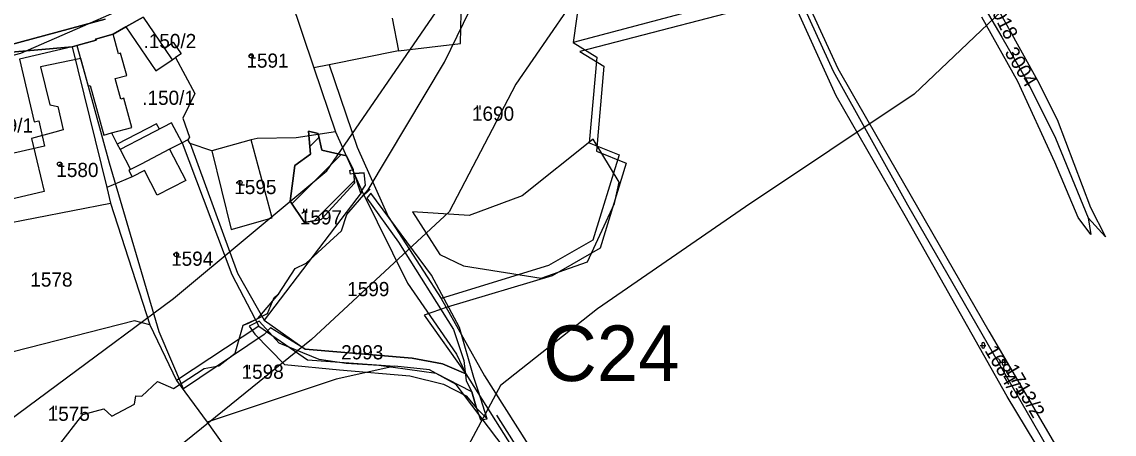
# Model space of a CAD drawing. Extents: x -564810 to -550519, y -1045831 to -1034011.
# Drawn here: x -554012.6 to -553619.6, y -1037838.1 to -1037689.8 of the extents above; entities that cross this region are included whole.
import ezdxf

# ---------------------------------------------------------------- set-up
doc = ezdxf.new("R2010")
doc.units = 0
for name, color, linetype in [('Interakční prvky', 7, 'Continuous'), ('KN stav', 7, 'Continuous'), ('Obvod KPU', 7, 'Continuous'), ('označ pol cest', 7, 'Continuous'), ('Parcelní čísla', 7, 'Continuous'), ('Polní cesty stavající', 7, 'Continuous'), ('STG', 7, 'Continuous'), ('Vodní plocha', 7, 'Continuous'), ('vodní toky', 7, 'Continuous'), ('Vrstva 22', 7, 'Continuous'), ('Vrstva 33', 7, 'Continuous'), ('Vrstva 4', 7, 'Continuous'), ('zamokř ploch', 7, 'Continuous')]:
    doc.layers.add(name, color=color, linetype=linetype)

msp = doc.modelspace()

# ---------------------------------------------------------------- linework, layer by layer
at = {"layer": 'Interakční prvky'}
msp.add_lwpolyline([(-553841.79, -1037831.23), (-553697.83, -1038058.69), (-553643.78, -1038106.7)], dxfattribs=at)
at = {"layer": 'KN stav'}
for p, q in [((-553854.73, -1037697.64), (-553853.8, -1037658.19)), ((-553743.64, -1037657.08), (-553720.71, -1037707.5)), ((-553741.77, -1037657.08), (-553719.06, -1037706.56)), ((-553674.89, -1037669.86), (-553660.06, -1037695.35)), ((-553810.8, -1037673.21), (-553814.25, -1037697.2)), ((-553668.6, -1037672.13), (-553647.19, -1037710.95)), ((-553917.01, -1037678.13), (-553907.55, -1037706.36)), ((-553737.54, -1037676.84), (-553814.25, -1037697.2)), ((-553719.66, -1037716.36), (-553737.54, -1037676.84)), ((-554016.74, -1037698.02), (-553982.63, -1037688.82)), ((-553982.63, -1037688.82), (-554016.74, -1037698.02)), ((-553968.97, -1037688.08), (-553975.14, -1037691.62)), ((-553975.14, -1037691.62), (-553968.97, -1037688.08)), ((-553968.97, -1037688.08), (-553961.29, -1037699.33)), ((-553879.38, -1037688.47), (-553877.01, -1037700.18)), ((-553654.3, -1037711.22), (-553667.19, -1037688.1)), ((-553979.72, -1037694.24), (-553986, -1037695.97)), ((-553986, -1037695.97), (-553979.72, -1037694.24)), ((-553975.14, -1037691.62), (-553979.72, -1037694.24)), ((-553979.72, -1037694.24), (-553975.14, -1037691.62)), ((-553975.14, -1037691.62), (-553964.35, -1037707.42)), ((-553660.06, -1037695.35), (-553650.86, -1037711.16)), ((-553994.44, -1037698.83), (-554017.69, -1037700.77)), ((-554017.69, -1037700.77), (-553994.44, -1037698.83)), ((-553994.44, -1037698.83), (-554013.39, -1037703.24)), ((-553992.75, -1037698.33), (-553994.44, -1037698.83)), ((-553994.44, -1037698.83), (-553992.75, -1037698.33)), ((-553994.44, -1037698.83), (-553981.94, -1037749.42)), ((-553985.87, -1037696.44), (-553992.75, -1037698.33)), ((-553992.75, -1037698.33), (-553985.87, -1037696.44)), ((-553986, -1037695.97), (-553985.87, -1037696.44)), ((-553985.87, -1037696.44), (-553986, -1037695.97)), ((-553961.29, -1037699.33), (-553958.09, -1037697.15)), ((-553958.09, -1037697.15), (-553955.29, -1037701.24)), ((-553877.01, -1037700.18), (-553854.73, -1037697.64)), ((-553814.25, -1037697.2), (-553805.69, -1037702.54)), ((-554013.39, -1037703.24), (-554008.14, -1037725.77)), ((-553958.5, -1037703.43), (-553957.3, -1037702.61)), ((-553955.29, -1037701.24), (-553957.3, -1037702.61)), ((-553957.3, -1037702.61), (-553950.35, -1037715.52)), ((-553877.01, -1037700.18), (-553902.01, -1037705.24)), ((-553805.69, -1037702.54), (-553808.47, -1037733.31)), ((-553964.35, -1037707.42), (-553958.5, -1037703.43)), ((-553902.01, -1037705.24), (-553907.55, -1037706.36)), ((-553907.55, -1037706.36), (-553899.71, -1037729.33)), ((-553902.01, -1037705.24), (-553891.9, -1037734.88)), ((-553719.06, -1037706.56), (-553708.21, -1037725.45)), ((-553720.71, -1037707.5), (-553693.99, -1037755.63)), ((-553647.19, -1037710.95), (-553640.1, -1037724.97)), ((-553640.99, -1037740.25), (-553654.3, -1037711.22)), ((-553650.86, -1037711.16), (-553640.66, -1037731.58)), ((-553950.35, -1037715.52), (-553954.66, -1037724.43)), ((-553694.81, -1037759.51), (-553719.66, -1037716.36)), ((-554008.14, -1037725.77), (-554006.43, -1037725.38)), ((-554006.43, -1037725.38), (-554004.37, -1037734.49)), ((-553954.66, -1037724.43), (-553952.25, -1037731.25)), ((-553708.21, -1037725.45), (-553664.67, -1037801.06)), ((-553640.1, -1037724.97), (-553628.11, -1037756.57)), ((-553899.71, -1037729.33), (-553913.84, -1037731.52)), ((-553899.71, -1037729.33), (-553890.08, -1037750.79)), ((-554004.37, -1037734.49), (-554015.4, -1037736.99)), ((-553954.93, -1037733.29), (-553959.4, -1037735.61)), ((-553952.8, -1037732.18), (-553954.93, -1037733.29)), ((-553954.93, -1037733.29), (-553937.07, -1037780.67)), ((-553952.25, -1037731.25), (-553952.8, -1037732.18)), ((-553952.03, -1037733.6), (-553952.8, -1037732.18)), ((-553944.16, -1037736.23), (-553952.03, -1037733.6)), ((-553952.03, -1037733.6), (-553935.01, -1037780.21)), ((-553930.11, -1037732.23), (-553944.16, -1037736.23)), ((-553927.85, -1037731.72), (-553930.11, -1037732.23)), ((-553922.54, -1037760.31), (-553930.11, -1037732.23)), ((-553913.84, -1037731.52), (-553927.85, -1037731.72)), ((-553808.47, -1037733.31), (-553797.69, -1037737.62)), ((-553640.66, -1037731.58), (-553629, -1037760.31)), ((-553959.4, -1037735.61), (-553953.57, -1037746.81)), ((-553944.16, -1037736.23), (-553937.26, -1037764.51)), ((-553891.9, -1037734.88), (-553880.74, -1037759.79)), ((-553797.69, -1037737.62), (-553807.14, -1037768.34)), ((-553632.56, -1037760.13), (-553640.99, -1037740.25)), ((-553972.82, -1037745.53), (-553981.94, -1037749.42)), ((-553968.44, -1037743.25), (-553972.82, -1037745.53)), ((-553963.82, -1037752.14), (-553968.44, -1037743.25)), ((-553981.94, -1037749.42), (-553980.7, -1037754.99)), ((-553953.57, -1037746.81), (-553963.82, -1037752.14)), ((-553890.08, -1037750.79), (-553925.39, -1037797.06)), ((-553890.08, -1037750.79), (-553873.82, -1037783.79)), ((-554041.33, -1037766.82), (-553980.7, -1037754.99)), ((-553980.7, -1037754.99), (-553966.52, -1037798.77)), ((-553693.99, -1037755.63), (-553650.89, -1037830.33)), ((-553628.11, -1037756.57), (-553622.69, -1037767.07)), ((-553937.26, -1037764.51), (-553922.54, -1037760.31)), ((-553880.74, -1037759.79), (-553861.7, -1037789.25)), ((-553658.07, -1037824.52), (-553694.81, -1037759.51)), ((-553627.94, -1037766.27), (-553632.56, -1037760.13)), ((-553629, -1037760.31), (-553627.94, -1037766.27)), ((-553622.69, -1037767.07), (-553629, -1037760.31)), ((-553807.14, -1037768.34), (-553823.05, -1037777.47)), ((-553823.05, -1037777.47), (-553861.7, -1037789.25)), ((-553937.07, -1037780.67), (-553927.36, -1037799.27)), ((-553935.01, -1037780.21), (-553925.39, -1037797.06)), ((-553873.82, -1037783.79), (-553856.17, -1037809.33)), ((-553861.7, -1037789.25), (-553846.17, -1037817.17)), ((-553972.08, -1037797.39), (-554044.67, -1037815.82)), ((-553966.52, -1037798.77), (-553972.08, -1037797.39)), ((-553925.39, -1037797.06), (-553910.62, -1037807.56)), ((-553966.52, -1037798.77), (-553956.87, -1037818.76)), ((-553927.36, -1037799.27), (-553956.87, -1037818.76)), ((-553927.36, -1037799.27), (-553909.76, -1037811.31)), ((-553664.67, -1037801.06), (-553629.03, -1037861.88)), ((-553910.62, -1037807.56), (-553872.1, -1037810.73)), ((-553856.17, -1037809.33), (-553852.8, -1037816.35)), ((-553909.76, -1037811.31), (-553878.32, -1037813.69)), ((-553872.1, -1037810.73), (-553861.26, -1037812.79)), ((-553861.26, -1037812.79), (-553852.8, -1037816.35)), ((-553878.32, -1037813.69), (-553899.52, -1037818.33)), ((-553865.96, -1037815), (-553878.32, -1037813.69)), ((-553856.36, -1037820.25), (-553865.96, -1037815)), ((-553852.8, -1037816.35), (-553821.18, -1037866.37)), ((-553846.17, -1037817.17), (-553818.67, -1037860.27)), ((-553956.87, -1037818.76), (-553945.89, -1037833.82)), ((-553899.52, -1037818.33), (-553945.89, -1037833.82)), ((-553821.18, -1037866.37), (-553856.36, -1037820.25)), ((-553638.92, -1037856.33), (-553658.07, -1037824.52)), ((-553650.89, -1037830.33), (-553618.97, -1037885.65)), ((-553945.89, -1037833.82), (-553940.01, -1037842.06))]:
    msp.add_line(p, q, dxfattribs=at)
at = {"layer": 'Obvod KPU'}
for p, q in [((-553736.67, -1037680.93), (-553811.81, -1037700.43)), ((-553991.33, -1037702.98), (-554005.84, -1037705.93)), ((-553981.07, -1037740.66), (-553991.33, -1037702.98)), ((-553811.81, -1037700.43), (-553803.16, -1037705.71)), ((-554005.84, -1037705.93), (-554002.49, -1037719.62)), ((-553803.16, -1037705.71), (-553805.84, -1037736.34)), ((-554002.49, -1037719.62), (-553999.57, -1037720.24)), ((-553999.57, -1037720.24), (-553997.7, -1037728.63)), ((-554000.69, -1037729.44), (-554009.13, -1037731.73)), ((-553997.7, -1037728.63), (-554000.69, -1037729.44)), ((-554009.13, -1037731.73), (-554007.22, -1037739.73)), ((-553805.84, -1037736.34), (-553795.21, -1037740.63)), ((-554007.22, -1037739.73), (-554004.57, -1037750.84)), ((-553963.1, -1037801.3), (-553981.07, -1037740.66)), ((-553795.21, -1037740.63), (-553804.53, -1037771.2)), ((-554004.57, -1037750.84), (-554026.81, -1037756.1)), ((-553804.53, -1037771.2), (-553821.75, -1037781.17)), ((-553821.75, -1037781.17), (-553859.61, -1037792.46)), ((-553859.61, -1037792.46), (-553867.77, -1037795.33)), ((-553867.77, -1037795.33), (-553852.8, -1037816.35)), ((-553954.36, -1037821.74), (-553963.1, -1037801.3)), ((-553923.06, -1037799.85), (-553925.39, -1037802.29)), ((-553910.62, -1037807.56), (-553923.06, -1037799.85)), ((-553925.39, -1037802.29), (-553954.36, -1037821.74)), ((-553872.1, -1037810.73), (-553910.62, -1037807.56)), ((-553861.26, -1037812.79), (-553872.1, -1037810.73)), ((-553852.8, -1037816.35), (-553861.26, -1037812.79))]:
    msp.add_line(p, q, dxfattribs=at)
at = {"layer": 'Polní cesty stavající'}
for p, q in [((-553892.98, -1037744.29), (-553889.4, -1037744.13)), ((-553889.4, -1037744.13), (-553892.98, -1037744.29)), ((-553892.98, -1037744.29), (-553890.76, -1037751.31)), ((-553888.93, -1037748.59), (-553889.4, -1037744.13)), ((-553890.76, -1037751.31), (-553888.93, -1037748.59)), ((-553886.98, -1037751.46), (-553888.48, -1037753.24)), ((-553888.48, -1037753.24), (-553877, -1037769.08)), ((-553865.14, -1037780.87), (-553886.98, -1037751.46)), ((-553877, -1037769.08), (-553857.27, -1037800.49)), ((-553855.06, -1037799.74), (-553865.14, -1037780.87)), ((-553857.27, -1037800.49), (-553853.5, -1037811.61)), ((-553849.96, -1037817.68), (-553855.06, -1037799.74)), ((-553853.5, -1037811.61), (-553852.76, -1037818.96)), ((-553852.76, -1037818.96), (-553850.68, -1037822.86)), ((-553848.24, -1037822.74), (-553849.96, -1037817.68)), ((-553845.14, -1037832.64), (-553848.24, -1037822.74))]:
    msp.add_line(p, q, dxfattribs=at)
msp.add_lwpolyline([(-553927.13, -1037797.48), (-553930.82, -1037799.22), (-553928.75, -1037802.19), (-553918.12, -1037813.03), (-553898.28, -1037814.98), (-553873, -1037817.15), (-553860.9, -1037820.15), (-553852.72, -1037824.32), (-553849, -1037828.71), (-553850.68, -1037822.86), (-553863.54, -1037816.25), (-553884.12, -1037813.37), (-553895.84, -1037812.66), (-553905.65, -1037811.21), (-553920.04, -1037805.34)], close=True, dxfattribs=at)
for points in [[(-553850.68, -1037822.86), (-553849, -1037828.71)], [(-553849, -1037828.71), (-553847.55, -1037832.99), (-553845.14, -1037832.64)], [(-553849, -1037828.71), (-553845.14, -1037832.64)]]:
    msp.add_lwpolyline(points, dxfattribs=at)
at = {"layer": 'STG'}
for points in [[(-553734.4, -1037542.11), (-553748.55, -1037554.15), (-553765.08, -1037568.85), (-553766.92, -1037589.06), (-553781.62, -1037625.81), (-553798.15, -1037658.89), (-553834.89, -1037712.18), (-553858.78, -1037758.12), (-553908.38, -1037804.06), (-553956.14, -1037842.65), (-554002.07, -1037864.7), (-554057.18, -1037899.61), (-554110.46, -1037952.9), (-554099.44, -1037989.66), (-554073.72, -1038028.25), (-554022.28, -1038059.48), (-553969, -1038094.4), (-553923.07, -1038131.15), (-553875.31, -1038175.25), (-553855.1, -1038212)], [(-554411.74, -1038002.52), (-554288.66, -1037974.96), (-554228.03, -1037954.74), (-554158.22, -1037927.18), (-554084.74, -1037881.24), (-554035.14, -1037846.32), (-553957.98, -1037789.36), (-553902.87, -1037743.42), (-553862.45, -1037684.62), (-553836.73, -1037644.19), (-553825.71, -1037609.27), (-553902.87, -1037647.86), (-553941.44, -1037669.92), (-554013.09, -1037701.15), (-554090.25, -1037721.37), (-554149.04, -1037743.42), (-554218.85, -1037754.44), (-554281.31, -1037763.63), (-554336.42, -1037765.47)], [(-553605.26, -1037653.38), (-553653.02, -1037679.1), (-553691.6, -1037715.85), (-553752.22, -1037756.28), (-553805.5, -1037793.03), (-553840.4, -1037820.6), (-553867.96, -1037872.05), (-553867.96, -1037912.48), (-553833.06, -1037943.72), (-553796.31, -1037965.77), (-553765.08, -1037997.01), (-553743.04, -1038041.11), (-553737.53, -1038098.07), (-553746.71, -1038151.36), (-553746.71, -1038197.3), (-553715.48, -1038226.71), (-553685.23, -1038221.35), (-553672.37, -1038215.84), (-553636.49, -1038200.98), (-553592.95, -1038151.27)]]:
    msp.add_lwpolyline(points, dxfattribs=at)
at = {"layer": 'Vodní plocha'}
for p, q in [((-553905.91, -1037729.97), (-553909.43, -1037729.09)), ((-553909.43, -1037729.09), (-553908.75, -1037737.44)), ((-553904.65, -1037735.91), (-553905.91, -1037729.97)), ((-553908.98, -1037734.65), (-553905.63, -1037731.3)), ((-553915.41, -1037755.22), (-553897.72, -1037737.53)), ((-553908.75, -1037737.44), (-553914.38, -1037741.49)), ((-553895.81, -1037737.98), (-553904.65, -1037735.91)), ((-553893.36, -1037742.93), (-553895.81, -1037737.98)), ((-553914.38, -1037741.49), (-553916.04, -1037754.29)), ((-553894.62, -1037743.31), (-553893.36, -1037742.93)), ((-553894.29, -1037744.57), (-553894.62, -1037743.31)), ((-553892.98, -1037744.29), (-553894.29, -1037744.57)), ((-553892.87, -1037747.79), (-553892.98, -1037744.29)), ((-553907.39, -1037761.34), (-553892.9, -1037746.85)), ((-553904.82, -1037760.91), (-553892.87, -1037747.79)), ((-553916.04, -1037754.29), (-553910.89, -1037761.93)), ((-553910.89, -1037761.93), (-553904.82, -1037760.91))]:
    msp.add_line(p, q, dxfattribs=at)
at = {"layer": 'vodní toky'}
for p, q in [((-553807.07, -1037732.03), (-553832.63, -1037752.43)), ((-553797.73, -1037747.47), (-553807.07, -1037732.03)), ((-553799.38, -1037755.11), (-553797.73, -1037747.47)), ((-553832.63, -1037752.43), (-553851.65, -1037759.43)), ((-553851.65, -1037759.43), (-553871.98, -1037758.16)), ((-553871.98, -1037758.16), (-553862.17, -1037773.42)), ((-553809.07, -1037776.13), (-553799.38, -1037755.11)), ((-553862.17, -1037773.42), (-553853.67, -1037777.61)), ((-553853.67, -1037777.61), (-553825.77, -1037781.97)), ((-553825.77, -1037781.97), (-553809.07, -1037776.13))]:
    msp.add_line(p, q, dxfattribs=at)
msp.add_lwpolyline([(-553999.34, -1037842.32), (-553990.58, -1037831.07), (-553983.1, -1037828.99), (-553980.15, -1037831.66), (-553972.02, -1037827.32), (-553971.55, -1037824.36), (-553969.34, -1037824.46), (-553963.73, -1037819.12), (-553957.98, -1037821.65), (-553947.02, -1037814.43), (-553941.64, -1037813.51), (-553935.83, -1037808.96), (-553932.89, -1037798.85), (-553931.28, -1037798.28), (-553927.61, -1037796.47), (-553924.2, -1037794.7), (-553921.77, -1037788.97), (-553920.19, -1037787.7), (-553914.27, -1037778.54), (-553910.26, -1037776.62), (-553897.52, -1037764.92), (-553895.69, -1037759.04), (-553890.34, -1037752.99), (-553887.21, -1037749.93)], dxfattribs=at)
at = {"layer": 'Vrstva 33'}
msp.add_lwpolyline([(-553999.34, -1037842.32), (-553990.58, -1037831.07), (-553983.1, -1037828.99), (-553980.15, -1037831.66), (-553972.02, -1037827.32), (-553971.55, -1037824.36), (-553969.34, -1037824.46), (-553963.73, -1037819.12), (-553957.98, -1037821.65), (-553947.02, -1037814.43), (-553941.64, -1037813.51), (-553935.83, -1037808.96), (-553932.89, -1037798.85), (-553927.61, -1037796.47), (-553920.19, -1037787.7), (-553914.27, -1037778.54), (-553910.26, -1037776.62), (-553897.52, -1037764.92), (-553895.69, -1037759.04), (-553890.34, -1037752.99), (-553888.01, -1037750.27), (-553860.54, -1037704.27), (-553840.02, -1037662.15)], dxfattribs=at)
msp.add_lwpolyline([(-553908.75, -1037737.44), (-553909.43, -1037729.09), (-553905.91, -1037729.97), (-553904.65, -1037735.91), (-553895.81, -1037737.98), (-553893.36, -1037742.93), (-553892.87, -1037747.79), (-553904.82, -1037760.91), (-553910.89, -1037761.93), (-553916.04, -1037754.29), (-553914.38, -1037741.49)], close=True, dxfattribs=at)
at = {"layer": 'Vrstva 4'}
for p, q in [((-553977.78, -1037701.31), (-553979.73, -1037694.24)), ((-553992.75, -1037698.33), (-553988.74, -1037712.89)), ((-553977.04, -1037701.1), (-553977.78, -1037701.31)), ((-553974.84, -1037709.08), (-553977.04, -1037701.1)), ((-553961.29, -1037699.33), (-553958.5, -1037703.42)), ((-553979, -1037710.22), (-553974.84, -1037709.08)), ((-553976.96, -1037717.61), (-553979, -1037710.22)), ((-553988.74, -1037712.89), (-553987.93, -1037712.66)), ((-553987.93, -1037712.66), (-553983.02, -1037730.5)), ((-553975.86, -1037717.3), (-553976.96, -1037717.61)), ((-553972.98, -1037727.74), (-553975.86, -1037717.3)), ((-553964.09, -1037726.43), (-553978.21, -1037733.77)), ((-553958.66, -1037726.11), (-553977.19, -1037735.74)), ((-553963.06, -1037728.4), (-553964.09, -1037726.43)), ((-553954.93, -1037733.28), (-553958.66, -1037726.11)), ((-553983.02, -1037730.5), (-553980.3, -1037729.75)), ((-553980.3, -1037729.75), (-553972.98, -1037727.74)), ((-553980.3, -1037729.75), (-553978.21, -1037733.77)), ((-553978.21, -1037733.77), (-553977.19, -1037735.74)), ((-553977.19, -1037735.74), (-553973.46, -1037742.91)), ((-553959.4, -1037735.6), (-553969.64, -1037740.93)), ((-553969.64, -1037740.93), (-553973.46, -1037742.91)), ((-553973.46, -1037742.91), (-553974.02, -1037743.21)), ((-553974.02, -1037743.21), (-553972.82, -1037745.53))]:
    msp.add_line(p, q, dxfattribs=at)
at = {"layer": 'zamokř ploch'}
for p, q in [((-553930.05, -1037702.79), (-553928.45, -1037702.79)), ((-553848.74, -1037719.87), (-553848.74, -1037721.37)), ((-553847.74, -1037719.87), (-553847.74, -1037721.37)), ((-553998.99, -1037741.71), (-553997.39, -1037741.71)), ((-553934.09, -1037748.36), (-553932.49, -1037748.36)), ((-553911.19, -1037757.01), (-553911.19, -1037758.51)), ((-553910.19, -1037757.01), (-553910.19, -1037758.51)), ((-553956.93, -1037774.29), (-553955.33, -1037774.29)), ((-553667.76, -1037806.16), (-553665.76, -1037806.16)), ((-553667.26, -1037805.66), (-553667.26, -1037806.66)), ((-553666.26, -1037805.66), (-553666.26, -1037806.66)), ((-553931.76, -1037813.27), (-553931.76, -1037814.77)), ((-553930.76, -1037813.27), (-553930.76, -1037814.77)), ((-553660.42, -1037812.26), (-553658.42, -1037812.26)), ((-553659.92, -1037811.76), (-553659.92, -1037812.76)), ((-553658.92, -1037811.76), (-553658.92, -1037812.76)), ((-554001.32, -1037827.9), (-554001.32, -1037829.4)), ((-554000.32, -1037827.9), (-554000.32, -1037829.4))]:
    msp.add_line(p, q, dxfattribs=at)
for centre in [(-553930.05, -1037702.04), (-553998.99, -1037740.96), (-553934.09, -1037747.61), (-553956.93, -1037773.54)]:
    msp.add_circle(centre, 0.75, dxfattribs=at)
for centre, start, end in [((-553666.76, -1037805.66), 0, 180), ((-553666.76, -1037806.66), 180, 0), ((-553659.42, -1037811.76), 0, 180), ((-553659.42, -1037812.76), 180, 0)]:
    msp.add_arc(centre, 0.5, start, end, dxfattribs=at)

# ---------------------------------------------------------------- texts
at = {"layer": 'označ pol cest'}
msp.add_text('C24', height=20, dxfattribs=at).set_placement((-553825.04, -1037819))
at = {"layer": 'Parcelní čísla'}
for s, rotation, p in [('3018', 296.9015, (-553665.38, -1037683.08)), ('3004', 301.4704, (-553659.21, -1037700.82)), ('1684/3', 300.5337, (-553666.35, -1037808.02)), ('1713/2', 300.2947, (-553659.18, -1037814.72))]:
    msp.add_text(s, height=5.1, rotation=rotation, dxfattribs=at).set_placement(p)
for s, p in [('1591', (-553931.77, -1037706.28)), ('1690', (-553850.64, -1037725.36)), ('1580', (-554000.16, -1037745.61)), ('1595', (-553936.14, -1037751.75)), ('1597', (-553912.55, -1037762.67)), ('1594', (-553958.86, -1037777.54)), ('1578', (-554009.5, -1037785.04)), ('1599', (-553895.51, -1037788.46)), ('2993', (-553897.69, -1037811.2)), ('1598', (-553933.52, -1037818.19)), ('1575', (-554003.27, -1037833.3))]:
    msp.add_text(s, height=5.1, dxfattribs=at).set_placement(p)
at = {"layer": 'Vrstva 22'}
for s, p in [('.150/2', (-553968.79, -1037699.24)), ('.150/1', (-553969.25, -1037719.65)), ('.149/1', (-554027.5, -1037729.63))]:
    msp.add_text(s, height=5.1, dxfattribs=at).set_placement(p)

doc.saveas('drawing.dxf')
